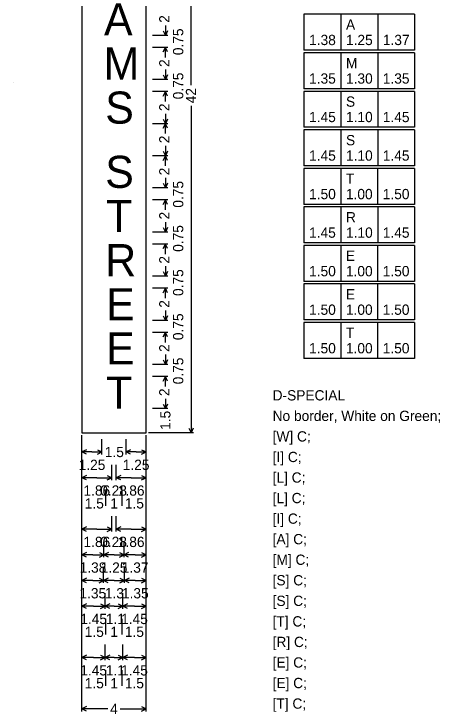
# Model space of a CAD drawing. Extents: x -16.4 to 26.5, y -12.9 to 9.1.
# Drawn here: x -6.13 to -1.07, y -7.92 to 0.39 of the extents above; entities that cross this region are included whole.
import ezdxf

# ---------------------------------------------------------------- set-up
doc = ezdxf.new("R2010")
doc.units = 0
doc.layers.add('PM_P_Text', color=7, linetype='Continuous')
doc.layers.add('SH_Text', color=7, linetype='Continuous')

msp = doc.modelspace()

# ---------------------------------------------------------------- linework, layer by layer
at = {"layer": 'PM_P_Text'}
msp.add_line((-6.132, -0.4292), (-6.132, -0.4292), dxfattribs=at)
at = {"layer": 'SH_Text'}
for p, q in [((-4.0297, -0.4573), (-4.0297, 3.4207)), ((-2.6881, 0.3848), (-2.6881, -0.0419)), ((-1.375, 0.3848), (-2.6881, 0.3848)), ((-2.2502, 0.3848), (-2.2502, -0.0419)), ((-1.8124, 0.3848), (-1.8124, -0.0419)), ((-1.375, 0.3848), (-1.375, -0.0419)), ((-4.3345, 0.2529), (-4.3345, 0.1346)), ((-4.3618, 0.189), (-4.3345, 0.1346)), ((-4.3073, 0.189), (-4.3345, 0.1346)), ((-4.304, 0.1346), (-4.4869, 0.1346)), ((-4.304, -0.0083), (-4.4869, -0.0083)), ((-4.3618, -0.0628), (-4.3345, -0.0083)), ((-4.3345, -0.1266), (-4.3345, -0.0083)), ((-4.3073, -0.0628), (-4.3345, -0.0083)), ((-1.375, -0.0419), (-2.6881, -0.0419)), ((-2.6881, -0.0724), (-2.6881, -0.4991)), ((-1.375, -0.0724), (-2.6881, -0.0724)), ((-2.2502, -0.0724), (-2.2502, -0.4991)), ((-1.813, -0.0724), (-1.813, -0.4991)), ((-1.375, -0.0724), (-1.375, -0.4991)), ((-4.3345, -0.271), (-4.3345, -0.3893)), ((-4.304, -0.3893), (-4.4869, -0.3893)), ((-4.3618, -0.3348), (-4.3345, -0.3893)), ((-4.3073, -0.3348), (-4.3345, -0.3893)), ((-4.304, -0.5322), (-4.4869, -0.5322)), ((-4.3618, -0.5867), (-4.3345, -0.5322)), ((-4.3345, -0.6505), (-4.3345, -0.5322)), ((-4.3073, -0.5867), (-4.3345, -0.5322)), ((-1.375, -0.4991), (-2.6881, -0.4991)), ((-2.6881, -0.5296), (-2.6881, -0.9563)), ((-1.375, -0.5296), (-2.6881, -0.5296)), ((-2.2502, -0.5296), (-2.2502, -0.9563)), ((-1.813, -0.5296), (-1.813, -0.9563)), ((-1.375, -0.5296), (-1.375, -0.9563)), ((-4.0297, -0.7023), (-4.0297, -4.5803)), ((-4.3345, -0.7949), (-4.3345, -0.9132)), ((-4.304, -0.9132), (-4.4869, -0.9132)), ((-4.3618, -0.8587), (-4.3345, -0.9132)), ((-4.3618, -0.9677), (-4.3345, -0.9132)), ((-4.3073, -0.8587), (-4.3345, -0.9132)), ((-4.3345, -1.0315), (-4.3345, -0.9132)), ((-4.3073, -0.9677), (-4.3345, -0.9132)), ((-1.375, -0.9563), (-2.6881, -0.9563)), ((-2.6881, -0.9868), (-2.6881, -1.4135)), ((-1.375, -0.9868), (-2.6881, -0.9868)), ((-2.2502, -0.9868), (-2.2502, -1.4135)), ((-1.813, -0.9868), (-1.813, -1.4135)), ((-1.375, -0.9868), (-1.375, -1.4135)), ((-4.3618, -1.2397), (-4.3345, -1.2942)), ((-4.3345, -1.1759), (-4.3345, -1.2942)), ((-4.3073, -1.2397), (-4.3345, -1.2942)), ((-4.304, -1.2942), (-4.4869, -1.2942)), ((-4.3618, -1.3487), (-4.3345, -1.2942)), ((-4.3345, -1.4125), (-4.3345, -1.2942)), ((-4.3073, -1.3487), (-4.3345, -1.2942)), ((-1.375, -1.4135), (-2.6881, -1.4135)), ((-2.6881, -1.444), (-2.6881, -1.8707)), ((-1.3763, -1.444), (-2.6881, -1.444)), ((-2.2509, -1.444), (-2.2509, -1.8707)), ((-1.8135, -1.444), (-1.8135, -1.8707)), ((-1.3763, -1.444), (-1.3763, -1.8707)), ((-4.3345, -1.5569), (-4.3345, -1.6752)), ((-4.3618, -1.6207), (-4.3345, -1.6752)), ((-4.3073, -1.6207), (-4.3345, -1.6752)), ((-4.304, -1.6752), (-4.4869, -1.6752)), ((-4.304, -1.8181), (-4.4869, -1.8181)), ((-4.3618, -1.8725), (-4.3345, -1.8181)), ((-4.3345, -1.9364), (-4.3345, -1.8181)), ((-4.3073, -1.8725), (-4.3345, -1.8181)), ((-1.3763, -1.8707), (-2.6881, -1.8707)), ((-2.6881, -1.9012), (-2.6881, -2.3279)), ((-1.375, -1.9012), (-2.6881, -1.9012)), ((-2.2502, -1.9012), (-2.2502, -2.3279)), ((-1.813, -1.9012), (-1.813, -2.3279)), ((-1.375, -1.9012), (-1.375, -2.3279)), ((-4.3618, -2.1446), (-4.3345, -2.1991)), ((-4.3345, -2.0808), (-4.3345, -2.1991)), ((-4.3073, -2.1446), (-4.3345, -2.1991)), ((-4.304, -2.1991), (-4.4869, -2.1991)), ((-4.304, -2.3419), (-4.4869, -2.3419)), ((-4.3618, -2.3964), (-4.3345, -2.3419)), ((-4.3345, -2.4602), (-4.3345, -2.3419)), ((-4.3073, -2.3964), (-4.3345, -2.3419)), ((-1.375, -2.3279), (-2.6881, -2.3279)), ((-2.6881, -2.3584), (-2.6881, -2.7851)), ((-1.3763, -2.3584), (-2.6881, -2.3584)), ((-2.2509, -2.3584), (-2.2509, -2.7851)), ((-1.8135, -2.3584), (-1.8135, -2.7851)), ((-1.3763, -2.3584), (-1.3763, -2.7851)), ((-4.3345, -2.6046), (-4.3345, -2.7229)), ((-4.304, -2.7229), (-4.4869, -2.7229)), ((-4.3618, -2.6685), (-4.3345, -2.7229)), ((-4.3073, -2.6685), (-4.3345, -2.7229)), ((-1.3763, -2.7851), (-2.6881, -2.7851)), ((-2.6881, -2.8156), (-2.6881, -3.2423)), ((-1.3763, -2.8156), (-2.6881, -2.8156)), ((-2.2509, -2.8156), (-2.2509, -3.2423)), ((-1.8135, -2.8156), (-1.8135, -3.2423)), ((-1.3763, -2.8156), (-1.3763, -3.2423)), ((-4.304, -2.8658), (-4.4869, -2.8658)), ((-4.3618, -2.9203), (-4.3345, -2.8658)), ((-4.3345, -2.9841), (-4.3345, -2.8658)), ((-4.3073, -2.9203), (-4.3345, -2.8658)), ((-4.3345, -3.1285), (-4.3345, -3.2468)), ((-4.3618, -3.1923), (-4.3345, -3.2468)), ((-4.3073, -3.1923), (-4.3345, -3.2468)), ((-4.304, -3.2468), (-4.4869, -3.2468)), ((-1.3763, -3.2423), (-2.6881, -3.2423)), ((-2.6881, -3.2728), (-2.6881, -3.6995)), ((-1.3763, -3.2728), (-2.6881, -3.2728)), ((-2.2509, -3.2728), (-2.2509, -3.6995)), ((-1.8135, -3.2728), (-1.8135, -3.6995)), ((-1.3763, -3.2728), (-1.3763, -3.6995)), ((-4.304, -3.3897), (-4.4869, -3.3897)), ((-4.3618, -3.4442), (-4.3345, -3.3897)), ((-4.3345, -3.508), (-4.3345, -3.3897)), ((-4.3073, -3.4442), (-4.3345, -3.3897)), ((-4.3345, -3.6524), (-4.3345, -3.7707)), ((-4.3618, -3.7162), (-4.3345, -3.7707)), ((-4.3073, -3.7162), (-4.3345, -3.7707)), ((-1.3763, -3.6995), (-2.6881, -3.6995)), ((-4.304, -3.7707), (-4.4869, -3.7707)), ((-4.304, -3.9136), (-4.4869, -3.9136)), ((-4.3618, -3.968), (-4.3345, -3.9136)), ((-4.3345, -4.0319), (-4.3345, -3.9136)), ((-4.3073, -3.968), (-4.3345, -3.9136)), ((-4.3345, -4.1763), (-4.3345, -4.2946)), ((-4.304, -4.2946), (-4.4869, -4.2946)), ((-4.304, -4.2946), (-4.4869, -4.2946)), ((-4.3618, -4.2401), (-4.3345, -4.2946)), ((-4.3073, -4.2401), (-4.3345, -4.2946)), ((-4.057, -4.5258), (-4.0297, -4.5803)), ((-4.0025, -4.5258), (-4.0297, -4.5803)), ((-5.3251, -7.8874), (-5.3251, -4.6108)), ((-4.5631, -7.8874), (-4.5631, -4.6108)), ((-3.9992, -4.5803), (-4.5326, -4.5803)), ((-4.304, -4.5803), (-4.4869, -4.5803)), ((-5.3251, -4.8394), (-5.3251, -4.6565)), ((-5.087, -4.8394), (-5.087, -4.6565)), ((-4.8012, -4.8394), (-4.8012, -4.6565)), ((-4.8012, -4.8394), (-4.8012, -4.6565)), ((-4.5631, -4.8394), (-4.5631, -4.6565)), ((-5.2706, -4.7817), (-5.3251, -4.8089)), ((-5.2061, -4.8089), (-5.3251, -4.8089)), ((-5.2706, -4.8362), (-5.3251, -4.8089)), ((-5.2061, -4.8089), (-5.087, -4.8089)), ((-5.1415, -4.7817), (-5.087, -4.8089)), ((-5.1415, -4.8362), (-5.087, -4.8089)), ((-4.7468, -4.7817), (-4.8012, -4.8089)), ((-4.6822, -4.8089), (-4.8012, -4.8089)), ((-4.7468, -4.8362), (-4.8012, -4.8089)), ((-4.6822, -4.8089), (-4.5631, -4.8089)), ((-4.6176, -4.7817), (-4.5631, -4.8089)), ((-4.6176, -4.8362), (-4.5631, -4.8089)), ((-5.3251, -5.1442), (-5.3251, -4.9613)), ((-4.971, -5.1442), (-4.971, -4.9613)), ((-4.9173, -5.1442), (-4.9173, -4.9613)), ((-4.9173, -5.1442), (-4.9173, -4.9613)), ((-4.5631, -5.1442), (-4.5631, -4.9613)), ((-5.2706, -5.0865), (-5.3251, -5.1137)), ((-5.148, -5.1137), (-5.3251, -5.1137)), ((-5.2706, -5.141), (-5.3251, -5.1137)), ((-5.148, -5.1137), (-4.971, -5.1137)), ((-5.0255, -5.0865), (-4.971, -5.1137)), ((-5.0255, -5.141), (-4.971, -5.1137)), ((-4.8628, -5.0865), (-4.9173, -5.1137)), ((-4.7403, -5.1137), (-4.9173, -5.1137)), ((-4.8628, -5.141), (-4.9173, -5.1137)), ((-4.7403, -5.1137), (-4.5631, -5.1137)), ((-4.6176, -5.0865), (-4.5631, -5.1137)), ((-4.6176, -5.141), (-4.5631, -5.1137)), ((-5.3251, -5.449), (-5.3251, -5.2661)), ((-5.0394, -5.449), (-5.0394, -5.2661)), ((-4.8489, -5.449), (-4.8489, -5.2661)), ((-4.8489, -5.449), (-4.8489, -5.2661)), ((-4.5631, -5.449), (-4.5631, -5.2661)), ((-5.3251, -5.7538), (-5.3251, -5.5709)), ((-4.971, -5.7538), (-4.971, -5.5709)), ((-4.9173, -5.7538), (-4.9173, -5.5709)), ((-4.9173, -5.7538), (-4.9173, -5.5709)), ((-4.5631, -5.7538), (-4.5631, -5.5709)), ((-5.2706, -5.6961), (-5.3251, -5.7233)), ((-5.148, -5.7233), (-5.3251, -5.7233)), ((-5.2706, -5.7506), (-5.3251, -5.7233)), ((-5.148, -5.7233), (-4.971, -5.7233)), ((-5.0255, -5.6961), (-4.971, -5.7233)), ((-5.0255, -5.7506), (-4.971, -5.7233)), ((-4.8628, -5.6961), (-4.9173, -5.7233)), ((-4.7403, -5.7233), (-4.9173, -5.7233)), ((-4.8628, -5.7506), (-4.9173, -5.7233)), ((-4.7403, -5.7233), (-4.5631, -5.7233)), ((-4.6176, -5.6961), (-4.5631, -5.7233)), ((-4.6176, -5.7506), (-4.5631, -5.7233)), ((-5.3251, -6.0586), (-5.3251, -5.8757)), ((-5.0632, -6.0586), (-5.0632, -5.8757)), ((-4.8251, -6.0586), (-4.8251, -5.8757)), ((-4.8251, -6.0586), (-4.8251, -5.8757)), ((-4.5631, -6.0586), (-4.5631, -5.8757)), ((-5.2706, -6.0009), (-5.3251, -6.0281)), ((-5.1941, -6.0281), (-5.3251, -6.0281)), ((-5.2706, -6.0554), (-5.3251, -6.0281)), ((-5.1941, -6.0281), (-5.0632, -6.0281)), ((-5.1177, -6.0009), (-5.0632, -6.0281)), ((-5.1177, -6.0554), (-5.0632, -6.0281)), ((-5.0087, -6.0009), (-5.0632, -6.0281)), ((-4.9441, -6.0281), (-5.0632, -6.0281)), ((-5.0087, -6.0554), (-5.0632, -6.0281)), ((-4.9441, -6.0281), (-4.8251, -6.0281)), ((-4.8795, -6.0009), (-4.8251, -6.0281)), ((-4.8795, -6.0554), (-4.8251, -6.0281)), ((-4.7706, -6.0009), (-4.8251, -6.0281)), ((-4.6942, -6.0281), (-4.8251, -6.0281)), ((-4.7706, -6.0554), (-4.8251, -6.0281)), ((-4.6942, -6.0281), (-4.5631, -6.0281)), ((-4.6176, -6.0009), (-4.5631, -6.0281)), ((-4.6176, -6.0554), (-4.5631, -6.0281)), ((-5.3251, -6.3634), (-5.3251, -6.1805)), ((-5.0676, -6.3634), (-5.0676, -6.1805)), ((-4.8207, -6.3634), (-4.8207, -6.1805)), ((-4.8207, -6.3634), (-4.8207, -6.1805)), ((-4.5631, -6.3634), (-4.5631, -6.1805)), ((-5.2706, -6.3057), (-5.3251, -6.3329)), ((-5.1222, -6.3057), (-5.0676, -6.3329)), ((-5.0131, -6.3057), (-5.0676, -6.3329)), ((-4.8752, -6.3057), (-4.8207, -6.3329)), ((-4.766, -6.3057), (-4.8207, -6.3329)), ((-4.6176, -6.3057), (-4.5631, -6.3329)), ((-5.1963, -6.3329), (-5.3251, -6.3329)), ((-5.2706, -6.3602), (-5.3251, -6.3329)), ((-5.1963, -6.3329), (-5.0676, -6.3329)), ((-5.1222, -6.3602), (-5.0676, -6.3329)), ((-4.9441, -6.3329), (-5.0676, -6.3329)), ((-5.0131, -6.3602), (-5.0676, -6.3329)), ((-4.9441, -6.3329), (-4.8207, -6.3329)), ((-4.8752, -6.3602), (-4.8207, -6.3329)), ((-4.6919, -6.3329), (-4.8207, -6.3329)), ((-4.766, -6.3602), (-4.8207, -6.3329)), ((-4.6919, -6.3329), (-4.5631, -6.3329)), ((-4.6176, -6.3602), (-4.5631, -6.3329)), ((-5.3251, -6.6682), (-5.3251, -6.4853)), ((-5.0483, -6.6682), (-5.0483, -6.4853)), ((-4.8399, -6.6682), (-4.8399, -6.4853)), ((-4.8399, -6.6682), (-4.8399, -6.4853)), ((-4.5631, -6.6682), (-4.5631, -6.4853)), ((-5.2706, -6.6105), (-5.3251, -6.6377)), ((-5.1866, -6.6377), (-5.3251, -6.6377)), ((-5.2706, -6.665), (-5.3251, -6.6377)), ((-5.1866, -6.6377), (-5.0483, -6.6377)), ((-5.1028, -6.6105), (-5.0483, -6.6377)), ((-5.1028, -6.665), (-5.0483, -6.6377)), ((-4.9938, -6.6105), (-5.0483, -6.6377)), ((-4.9441, -6.6377), (-5.0483, -6.6377)), ((-4.9938, -6.665), (-5.0483, -6.6377)), ((-4.9441, -6.6377), (-4.8399, -6.6377)), ((-4.8944, -6.6105), (-4.8399, -6.6377)), ((-4.8944, -6.665), (-4.8399, -6.6377)), ((-4.7854, -6.6105), (-4.8399, -6.6377)), ((-4.7016, -6.6377), (-4.8399, -6.6377)), ((-4.7854, -6.665), (-4.8399, -6.6377)), ((-4.7016, -6.6377), (-4.5631, -6.6377)), ((-4.6176, -6.6105), (-4.5631, -6.6377)), ((-4.6176, -6.665), (-4.5631, -6.6377)), ((-5.3251, -6.973), (-5.3251, -6.7901)), ((-5.0394, -6.973), (-5.0394, -6.7901)), ((-4.8489, -6.973), (-4.8489, -6.7901)), ((-4.8489, -6.973), (-4.8489, -6.7901)), ((-4.5631, -6.973), (-4.5631, -6.7901)), ((-5.3251, -7.2778), (-5.3251, -7.0949)), ((-5.0483, -7.2778), (-5.0483, -7.0949)), ((-4.8399, -7.2778), (-4.8399, -7.0949)), ((-4.8399, -7.2778), (-4.8399, -7.0949)), ((-4.5631, -7.2778), (-4.5631, -7.0949)), ((-5.2706, -7.2201), (-5.3251, -7.2473)), ((-5.1028, -7.2201), (-5.0483, -7.2473)), ((-4.9938, -7.2201), (-5.0483, -7.2473)), ((-4.8944, -7.2201), (-4.8399, -7.2473)), ((-4.7854, -7.2201), (-4.8399, -7.2473)), ((-4.6176, -7.2201), (-4.5631, -7.2473)), ((-5.1866, -7.2473), (-5.3251, -7.2473)), ((-5.2706, -7.2746), (-5.3251, -7.2473)), ((-5.1866, -7.2473), (-5.0483, -7.2473)), ((-5.1028, -7.2746), (-5.0483, -7.2473)), ((-4.9441, -7.2473), (-5.0483, -7.2473)), ((-4.9938, -7.2746), (-5.0483, -7.2473)), ((-4.9441, -7.2473), (-4.8399, -7.2473)), ((-4.8944, -7.2746), (-4.8399, -7.2473)), ((-4.7016, -7.2473), (-4.8399, -7.2473)), ((-4.7854, -7.2746), (-4.8399, -7.2473)), ((-4.7016, -7.2473), (-4.5631, -7.2473)), ((-4.6176, -7.2746), (-4.5631, -7.2473)), ((-5.3251, -7.5826), (-5.3251, -7.3997)), ((-5.0394, -7.5826), (-5.0394, -7.3997)), ((-4.8489, -7.5826), (-4.8489, -7.3997)), ((-4.8489, -7.5826), (-4.8489, -7.3997)), ((-4.5631, -7.5826), (-4.5631, -7.3997)), ((-5.2706, -7.8297), (-5.3251, -7.8569)), ((-5.0184, -7.8569), (-5.3251, -7.8569)), ((-5.2706, -7.8842), (-5.3251, -7.8569)), ((-4.8698, -7.8569), (-4.5631, -7.8569)), ((-4.6176, -7.8297), (-4.5631, -7.8569)), ((-4.6176, -7.8842), (-4.5631, -7.8569))]:
    msp.add_line(p, q, dxfattribs=at)
msp.add_lwpolyline([(-5.3251, -4.5803), (-4.5631, -4.5803), (-4.5631, 3.4207), (-5.3251, 3.4207), (-5.3251, -4.5803), (-5.3251, -4.5803)], dxfattribs=at)

# ---------------------------------------------------------------- texts
for s, height, p in [('A', 0.381, (-5.0632, 0.1346)), ('A', 0.1219, (-2.1892, 0.2019)), ('1.38', 0.12192, (-2.6272, 0.0191)), ('1.25', 0.12192, (-2.1892, 0.0191)), ('1.37', 0.12192, (-1.7514, 0.0191)), ('M', 0.381, (-5.0676, -0.3893)), ('M', 0.1219, (-2.1892, -0.2553)), ('1.35', 0.12192, (-2.6272, -0.4381)), ('1.30', 0.12192, (-2.1892, -0.4381)), ('1.35', 0.12192, (-1.752, -0.4381)), ('S', 0.381, (-5.0483, -0.9132)), ('S', 0.1219, (-2.1892, -0.7125)), ('1.45', 0.12192, (-2.6272, -0.8953)), ('1.10', 0.12192, (-2.1892, -0.8953)), ('1.45', 0.12192, (-1.752, -0.8953)), ('S', 0.1219, (-2.1892, -1.1697)), ('1.45', 0.12192, (-2.6272, -1.3525)), ('1.10', 0.12192, (-2.1892, -1.3525)), ('1.45', 0.12192, (-1.752, -1.3525)), ('S', 0.381, (-5.0483, -1.6752)), ('T', 0.1219, (-2.19, -1.6269)), ('1.50', 0.12192, (-2.6272, -1.8097)), ('1.00', 0.12192, (-2.19, -1.8097)), ('1.50', 0.12192, (-1.7526, -1.8097)), ('T', 0.381, (-5.0394, -2.1991)), ('R', 0.1219, (-2.1892, -2.0841)), ('1.45', 0.12192, (-2.6272, -2.2669)), ('1.10', 0.12192, (-2.1892, -2.2669)), ('1.45', 0.12192, (-1.752, -2.2669)), ('R', 0.381, (-5.0483, -2.7229)), ('E', 0.1219, (-2.19, -2.5413)), ('1.50', 0.12192, (-2.6272, -2.7241)), ('1.00', 0.12192, (-2.19, -2.7241)), ('1.50', 0.12192, (-1.7526, -2.7241)), ('E', 0.381, (-5.0394, -3.2468)), ('E', 0.1219, (-2.19, -2.9985)), ('1.50', 0.12192, (-2.6272, -3.1813)), ('1.00', 0.12192, (-2.19, -3.1813)), ('1.50', 0.12192, (-1.7526, -3.1813)), ('E', 0.381, (-5.0394, -3.7707)), ('T', 0.1219, (-2.19, -3.4557)), ('1.50', 0.12192, (-2.6272, -3.6385)), ('1.00', 0.12192, (-2.19, -3.6385)), ('1.50', 0.12192, (-1.7526, -3.6385)), ('T', 0.381, (-5.0394, -4.2946)), ('D-SPECIAL', 0.12192, (-3.0606, -4.1974)), ('No border, White on Green; ', 0.12192, (-3.0606, -4.4413)), ('[W] C; ', 0.12192, (-3.0606, -4.6851)), ('1.5', 0.12192, (-5.0533, -4.8699)), ('[I] C; ', 0.12192, (-3.0606, -4.9289)), ('1.25', 0.12192, (-5.364, -5.0223)), ('1.25', 0.12192, (-4.8401, -5.0223)), ('[L] C; ', 0.12192, (-3.0606, -5.1728)), ('1.86', 0.12192, (-5.3066, -5.3271)), ('0.28', 0.12192, (-5.1078, -5.3271)), ('1.86', 0.12192, (-4.8988, -5.3271)), ('[L] C; ', 0.12192, (-3.0606, -5.4166)), ('1.5', 0.12192, (-5.2914, -5.4795)), ('1', 0.1219, (-4.9874, -5.4795)), ('1.5', 0.12192, (-4.8152, -5.4795)), ('[I] C; ', 0.12192, (-3.0606, -5.6605)), ('1.86', 0.12192, (-5.3066, -5.9367)), ('0.28', 0.12192, (-5.1078, -5.9367)), ('1.86', 0.12192, (-4.8988, -5.9367)), ('[A] C; ', 0.12192, (-3.0606, -5.9043)), ('[M] C; ', 0.12192, (-3.0606, -6.1481)), ('1.38', 0.12192, (-5.3522, -6.2415)), ('1.25', 0.12192, (-5.102, -6.2415)), ('1.37', 0.12192, (-4.8517, -6.2415)), ('[S] C; ', 0.12192, (-3.0606, -6.392)), ('1.35', 0.12192, (-5.3545, -6.5463)), ('1.3', 0.12192, (-5.0529, -6.5463)), ('1.35', 0.12192, (-4.8498, -6.5463)), ('[S] C; ', 0.12192, (-3.0606, -6.6358)), ('1.45', 0.12192, (-5.3447, -6.8511)), ('1.1', 0.12192, (-5.0411, -6.8511)), ('1.45', 0.12192, (-4.8595, -6.8511)), ('[T] C; ', 0.12192, (-3.0606, -6.8797)), ('1.5', 0.12192, (-5.2914, -7.0035)), ('1', 0.1219, (-4.9874, -7.0035)), ('1.5', 0.12192, (-4.8152, -7.0035)), ('[R] C; ', 0.12192, (-3.0606, -7.1235)), ('[E] C; ', 0.12192, (-3.0606, -7.3673)), ('1.45', 0.12192, (-5.3447, -7.4607)), ('1.1', 0.12192, (-5.0411, -7.4607)), ('1.45', 0.12192, (-4.8595, -7.4607)), ('1.5', 0.12192, (-5.2914, -7.6131)), ('1', 0.1219, (-4.9874, -7.6131)), ('1.5', 0.12192, (-4.8152, -7.6131)), ('[E] C; ', 0.12192, (-3.0606, -7.6112)), ('4', 0.1219, (-4.9902, -7.9179)), ('[T] C; ', 0.12192, (-3.0606, -7.855))]:
    msp.add_text(s, height=height, dxfattribs=at).set_placement(p)
for s, height, p in [('2', 0.1219, (-4.2858, 0.2833)), ('0.75', 0.12192, (-4.1212, -0.1005)), ('2', 0.1219, (-4.2858, -0.2405)), ('0.75', 0.12192, (-4.1212, -0.6244)), ('42', 0.12192, (-3.9688, -0.6718)), ('2', 0.1219, (-4.2858, -0.7644)), ('2', 0.1219, (-4.2858, -1.1454)), ('2', 0.1219, (-4.2858, -1.5264)), ('0.75', 0.12192, (-4.1212, -1.9103)), ('2', 0.1219, (-4.2858, -2.0503)), ('0.75', 0.12192, (-4.1212, -2.4341)), ('2', 0.1219, (-4.2858, -2.5742)), ('0.75', 0.12192, (-4.1212, -2.958)), ('2', 0.1219, (-4.2858, -3.098)), ('0.75', 0.12192, (-4.1212, -3.4819)), ('2', 0.1219, (-4.2858, -3.6219)), ('0.75', 0.12192, (-4.1212, -4.0058)), ('2', 0.1219, (-4.2858, -4.1458)), ('1.5', 0.12192, (-4.2736, -4.5466))]:
    msp.add_text(s, height=height, rotation=90.00021, dxfattribs=at).set_placement(p)

doc.saveas('drawing.dxf')
